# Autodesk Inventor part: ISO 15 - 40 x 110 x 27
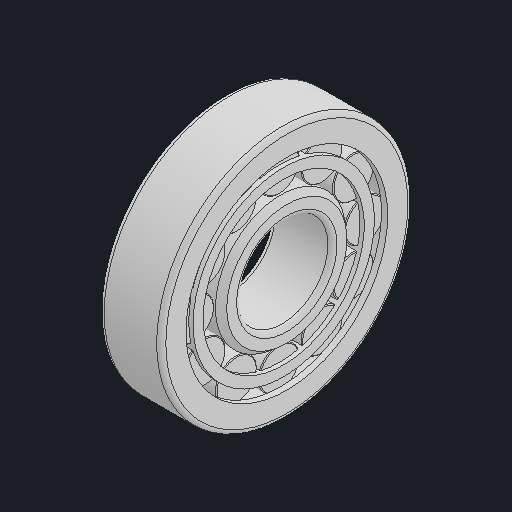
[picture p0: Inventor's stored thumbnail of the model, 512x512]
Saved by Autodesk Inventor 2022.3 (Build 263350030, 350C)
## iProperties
Created: 2020-09
Part Number: ISO 15 - 40 x 110 x 27
Material: Типовые
Document SubType Name: Modeling
Designer: Карташов
Density: 1 g/cm^3
Appearance: По умолчанию
Title: D:\мои документы\Ирина\_WorldSkills\2020_09 ФНЧ\Module A\GIVEN\ISO 15 - 40 x 110 x 27.stp
Author: Дом
Sending System: Autodesk Inventor 2021
Preprocessor: ST-DEVELOPER v18.1
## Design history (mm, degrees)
feature "Твердое тело2"
node "Твердое тело1"
